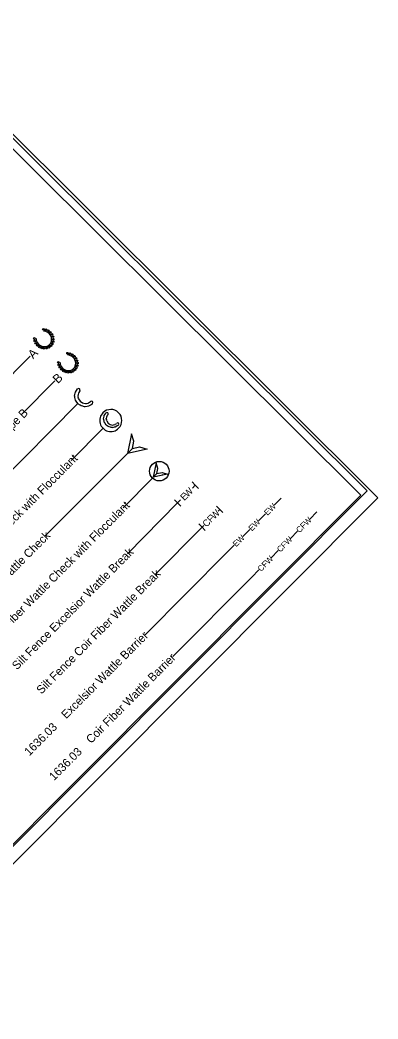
# Model space of a CAD drawing. Extents: x 1484932 to 1495672, y 495497 to 506262.
# Drawn here: x 1493934 to 1495672, y 501407 to 506262 of the extents above; entities that cross this region are included whole.
import ezdxf

# ---------------------------------------------------------------- set-up
doc = ezdxf.new("R2010")
doc.units = 0
for name, color, linetype in [('Scratch_Level_0', 7, 'Continuous'), ('Sheet Plot Border Inside CELL', 7, 'Continuous'), ('Sheet Plot Border Outside CELL', 7, 'Continuous')]:
    doc.layers.add(name, color=color, linetype=linetype)

msp = doc.modelspace()

# ---------------------------------------------------------------- linework, layer by layer
at = {"layer": 'Scratch_Level_0'}
for p, q in [((1493821.4, 504465.3), (1493982.8, 504627.8)), ((1493940.9, 504344.2), (1494103.3, 504507.7)), ((1494216.2, 504442.6), (1494214.6, 504434.7)), ((1494214.9, 504433.4), (1494214.6, 504434.7)), ((1494214.9, 504433.4), (1494216.3, 504427.5)), ((1494217.4, 504448.6), (1494216.2, 504442.6)), ((1494217.8, 504421), (1494216.3, 504427.5)), ((1494219.9, 504452.2), (1494217.4, 504448.6)), ((1494224.8, 504459.2), (1494219.9, 504452.2)), ((1493803.8, 503983.3), (1494214.6, 504397.5)), ((1494217.8, 504421), (1494226.2, 504409.1)), ((1494226.2, 504409.1), (1494226.2, 504409.1)), ((1494226.2, 504409.1), (1494237.7, 504401)), ((1494237.7, 504401), (1494244.2, 504399.5)), ((1494244.2, 504399.5), (1494252, 504397.7)), ((1494252, 504397.7), (1494257.6, 504398.9)), ((1494257.6, 504398.9), (1494265.6, 504400.6)), ((1494267.1, 504401.7), (1494265.6, 504400.6)), ((1494267.1, 504401.7), (1494275.6, 504407.5)), ((1494354, 504331.2), (1494352.7, 504324.7)), ((1494355, 504336.2), (1494354, 504331.2)), ((1494357.1, 504339.2), (1494355, 504336.2)), ((1494361.2, 504345.1), (1494357.1, 504339.2)), ((1494182.2, 504121.2), (1494337, 504277.7)), ((1494352.9, 504323.6), (1494352.7, 504324.7)), ((1494352.9, 504323.6), (1494354.1, 504318.6)), ((1494355.4, 504313.3), (1494354.1, 504318.6)), ((1494355.4, 504313.3), (1494362.4, 504303.3)), ((1494362.4, 504303.3), (1494362.4, 504303.3)), ((1494362.4, 504303.3), (1494372, 504296.5)), ((1494372, 504296.5), (1494377.4, 504295.2)), ((1494377.4, 504295.2), (1494383.9, 504293.7)), ((1494383.9, 504293.7), (1494388.5, 504294.8)), ((1494388.5, 504294.8), (1494395.2, 504296.2)), ((1494396.5, 504297.1), (1494395.2, 504296.2)), ((1494396.5, 504297.1), (1494403.6, 504301.9)), ((1494475.4, 504242.5), (1494475.4, 504242.5)), ((1494056.9, 503754.4), (1494456, 504155.9)), ((1494595, 504103.5), (1494595, 504103.5)), ((1494434, 503892), (1494576.6, 504035.9)), ((1494627.5, 504052.5), (1494626.5, 504051.8)), ((1494784.8, 504001.3), (1494769.3, 504016.8)), ((1494770.9, 503987.3), (1494784.8, 504001.3)), ((1494784.8, 504001.3), (1494800.4, 503985.8)), ((1495167.6, 503904.4), (1495201.7, 503938.8)), ((1494455.3, 503668.3), (1494699.3, 503915.4)), ((1494699.3, 503915.4), (1494683.7, 503930.9)), ((1494699.3, 503915.4), (1494713.2, 503929.4)), ((1494699.3, 503915.4), (1494714.8, 503899.9)), ((1494903.5, 503883.3), (1494887.9, 503898.8)), ((1494895.7, 503875.5), (1494903.5, 503883.3)), ((1494903.5, 503883.3), (1494919.1, 503867.8)), ((1495091.5, 503828), (1495125.7, 503862.3)), ((1495340.4, 503836.9), (1495374.6, 503871.3)), ((1494588.2, 503565.5), (1494817.9, 503797.3)), ((1494817.9, 503797.3), (1494802.3, 503812.8)), ((1494817.9, 503797.3), (1494825.6, 503805.1)), ((1494817.9, 503797.3), (1494833.5, 503781.8)), ((1495015.5, 503751.5), (1495049.6, 503785.9)), ((1495247, 503742.9), (1495281.1, 503777.3)), ((1494939.4, 503675.1), (1494973.6, 503709.5)), ((1494541.7, 503274.6), (1494939.4, 503675.1)), ((1495153.5, 503649), (1495187.6, 503683.4)), ((1494676.6, 503169.1), (1495060, 503555)), ((1495060, 503555), (1495094.2, 503589.4))]:
    msp.add_line(p, q, dxfattribs=at)
for points in [[(1493352.5, 506178.3), (1490172.1, 502984.8), (1492407.6, 500758.5), (1495587.9, 503952.1)], [(1494475.4, 504251.3), (1494456, 504155.9), (1494480, 504180), (1494487.3, 504214.6)], [(1494551.3, 504175.7), (1494456, 504155.9), (1494480, 504180), (1494514.6, 504187.4)], [(1494595, 504109.9), (1494580.8, 504040), (1494598.4, 504057.6), (1494603.7, 504083)], [(1494650.7, 504054.4), (1494580.8, 504040), (1494598.4, 504057.6), (1494623.7, 504063.1)]]:
    msp.add_lwpolyline(points, close=True, dxfattribs=at)
for points in [[(1494285.7, 504397.3), (1494278.7, 504392.4), (1494270.5, 504386.6), (1494266, 504385.6), (1494260.5, 504384.4), (1494250.8, 504382.2), (1494250.6, 504382.2), (1494248.2, 504382.7), (1494247.8, 504382.8), (1494242.6, 504383.9), (1494239, 504384.6), (1494231.1, 504386.3), (1494226.3, 504389.5), (1494214.6, 504397.4), (1494214.6, 504397.5), (1494206.4, 504409.5), (1494203.2, 504414.2), (1494201.9, 504420.4), (1494201.6, 504421.7), (1494200.6, 504426.9), (1494199.8, 504430.8), (1494199.6, 504431.8), (1494199.2, 504433.7), (1494199.2, 504433.8), (1494200.9, 504442), (1494202.5, 504449.2), (1494203.4, 504453.6), (1494208.8, 504461.7), (1494213.6, 504468.8)], [(1494412.1, 504293.5), (1494406.2, 504289.3), (1494399.3, 504284.5), (1494395.6, 504283.6), (1494391, 504282.6), (1494382.9, 504280.8), (1494382.7, 504280.9), (1494380.7, 504281.3), (1494380.4, 504281.3), (1494376.1, 504282.2), (1494373.1, 504282.9), (1494366.4, 504284.3), (1494362.5, 504286.9), (1494352.7, 504293.6), (1494352.7, 504293.6), (1494345.8, 504303.6), (1494343.1, 504307.6), (1494342.1, 504312.7), (1494341.9, 504313.8), (1494341, 504318.1), (1494340.3, 504321.4), (1494340.1, 504322.2), (1494339.8, 504323.8), (1494339.8, 504323.9), (1494341.3, 504330.7), (1494342.6, 504336.8), (1494343.3, 504340.4), (1494347.9, 504347.2), (1494351.8, 504353.1)]]:
    msp.add_lwpolyline(points, dxfattribs=at)
msp.add_circle((1494610.1, 504069.5), 47.4, dxfattribs=at)
for centre, radius, start, end in [((1494218.8, 504463.6), 7.38, 324.006, 135.1186), ((1494280.7, 504402.4), 7.18, 315.1186, 135.1186), ((1494374.8, 504315.7), 53.6, 135.1186, 315.1186), ((1494374.8, 504315.7), 53.6, 315.1186, 135.1186), ((1494356.2, 504348.7), 6.16, 324.006, 135.1186), ((1494407.8, 504297.7), 5.99, 315.1186, 135.1186)]:
    msp.add_arc(centre, radius, start, end, dxfattribs=at)
for centre, major_axis in [((1494047.9, 504758.9), (-3.01, 3)), ((1494003.4, 504714.2), (3.01, -3)), ((1494059.9, 504756.9), (-3.01, 3)), ((1494071.3, 504751.8), (-3.01, 3)), ((1494081.1, 504744.2), (-3.01, 3)), ((1494088.9, 504734.3), (-3.01, 3)), ((1494093.9, 504723), (-3.01, 3)), ((1494096, 504710.9), (-3.01, 3)), ((1494005.4, 504702.2), (3.01, -3)), ((1494010.5, 504690.9), (3.01, -3)), ((1494018.2, 504681), (3.01, -3)), ((1494028.1, 504673.3), (3.01, -3)), ((1494039.5, 504668.3), (3.01, -3)), ((1494051.5, 504666.3), (3.01, -3)), ((1494063.4, 504667.4), (3.01, -3)), ((1494074.4, 504671.7), (3.01, -3)), ((1494083.7, 504678.7), (3.01, -3)), ((1494090.7, 504688), (3.01, -3)), ((1494094.9, 504699), (3.01, -3)), ((1494164.7, 504642.5), (-3.01, 3)), ((1494176.7, 504640.5), (-3.01, 3)), ((1494188.1, 504635.5), (-3.01, 3)), ((1494198, 504627.8), (-3.01, 3)), ((1494205.7, 504617.9), (-3.01, 3)), ((1494120.2, 504597.9), (3.01, -3)), ((1494122.3, 504585.8), (3.01, -3)), ((1494127.4, 504574.5), (3.01, -3)), ((1494135.1, 504564.7), (3.01, -3)), ((1494207.6, 504571.6), (3.01, -3)), ((1494210.8, 504606.6), (-3.01, 3)), ((1494211.7, 504582.6), (3.01, -3)), ((1494212.8, 504594.6), (-3.01, 3)), ((1494145, 504557), (3.01, -3)), ((1494156.3, 504551.9), (3.01, -3)), ((1494168.4, 504549.9), (3.01, -3)), ((1494180.3, 504551.1), (3.01, -3)), ((1494191.3, 504555.3), (3.01, -3)), ((1494200.6, 504562.3), (3.01, -3))]:
    msp.add_ellipse(centre, major_axis=major_axis, ratio=0.927398, dxfattribs=at)
for centre in [(1494049.7, 504712.6), (1494166.5, 504596.2)]:
    msp.add_ellipse(centre, major_axis=(-27.9, 27.8), ratio=0.927398, start_param=0.785389, end_param=5.497624, dxfattribs=at)
at = {"layer": 'Sheet Plot Border Inside CELL'}
msp.add_lwpolyline([(1492087.5, 500426.4), (1495619.8, 503973.4), (1493373.6, 506210.2), (1489841.3, 502663.3)], close=True, dxfattribs=at)
at = {"layer": 'Sheet Plot Border Outside CELL'}
msp.add_lwpolyline([(1492102.5, 500356.3), (1495671.9, 503940.6), (1493340.6, 506262.2), (1489771.2, 502678)], close=True, dxfattribs=at)

# ---------------------------------------------------------------- texts
at = {"layer": 'Scratch_Level_0'}
for s, height, p in [('A', 42.9, (1493998, 504612.6)), ('B', 42.9, (1494118.5, 504492.6)), ('Rock Pipe Inlet Sediment Trap Type B', 40.704, (1493322.9, 503693)), ('Excelsior Wattle Check with Flocculant', 40.761, (1493557.3, 503464.8)), ('W', 33.1, (1494748, 503940.3)), ('E', 33.1, (1494731.7, 503924)), ('Coir Fiber Wattle Check with Flocculant', 40.761, (1493796.8, 503223.2)), ('EW', 28.58, (1495135.8, 503852.3)), ('F', 33.1, (1494861.5, 503817.1)), ('W', 33.1, (1494877.8, 503833.4)), ('CFW', 28.58, (1495291.2, 503767.2)), ('C', 33.1, (1494839.3, 503794.9)), ('EW', 28.58, (1495059.8, 503775.8)), ('Coir Fiber Wattle Check', 40.761, (1493676.2, 503343.2)), ('EW', 28.58, (1494983.7, 503699.4)), ('CFW', 28.58, (1495197.8, 503673.3)), ('Silt Fence Excelsior Wattle Break', 40.777, (1493919.3, 503101.2)), ('CFW', 28.58, (1495104.3, 503579.3)), ('Silt Fence Coir Fiber Wattle Break', 40.777, (1494037.9, 502983.1)), ('Excelsior Wattle Barrier', 40.777, (1494158.4, 502863)), ('Coir Fiber Wattle Barrier', 40.777, (1494279, 502743)), ('1636.03', 40.71, (1493979, 502683)), ('1636.03', 40.71, (1494099.5, 502562.9))]:
    msp.add_text(s, height=height, rotation=45.1186, dxfattribs=at).set_placement(p)

doc.saveas('drawing.dxf')
